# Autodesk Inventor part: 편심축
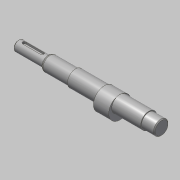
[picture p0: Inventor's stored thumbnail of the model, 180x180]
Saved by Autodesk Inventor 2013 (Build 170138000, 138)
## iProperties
Created: 2017-08
Part Number: 편심축
Material: 강철, 연강
Document SubType Name: Modeling
Designer: mduedu
Density: 7.86 g/cm^3
Mass: 338.399 g
Surface Area: 105.4 cm^2
Volume: 43.0533 cm^3
Author: mduedu
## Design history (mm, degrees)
sketch "스케치1"
  geometry: L1 (0, 0)-(168, 0); L2 (168, 0)-(168, 8.5); L3 (168, 8.5)-(153, 8.5); L4 (153, 8.5)-(153, 9.5); L5 (153, 9.5)-(67, 9.5); L6 (67, 9.5)-(67, 8.5); L7 (67, 8.5)-(35, 8.5); L8 (35, 8.5)-(35, 6); L9 (35, 6)-(0, 6); L10 (0, 6)-(0, 0)
  constraints: 20 end point, 6 parallel, 2 collinear, 2 perpendicular, 1 horizontal
  dimensions: "d0" = 168 distance of L1.start L1.end; "d1" = 17 diameter of L3 L1; "d2" = 19 diameter of L5 L1; "d3" = 12 diameter of L9 L1; "d4" = 35 distance of L8.end L9.end; "d5" = 15 distance of L2.end L3.end; "d6" = 86 distance of L4.end L5.end
revolve "회전1" sketch "스케치1" stored, may be unused: angle "d7" = 90 deg
node "작업 평면1"
sketch "스케치2"
  geometry: C1 r 9.5 at (0, 0) reference; C2 r 13 at (0, -3.5); 1 further point
  constraints: 1 centre point, 1 tangent, 1 vertical alignment
  dimensions: "d8" = 3.5 distance of point (0, 0) C2.centre
extrude "돌출1" join sketch "스케치2" stored distance "d9" = 18; taper "d10" = 0 deg
chamfer "모따기1" distance "d11" = 1; stored, may be unused: second distance "d12" = 2, angle "d13" = 45 deg
node "작업 평면2"
sketch "스케치3"
  geometry: L1 (10.5, -2)-(-10.5, -2); L2 (-10.5, -2)-(-10.5, 2); L3 (-10.5, 2)-(10.5, 2); L4 (10.5, 2)-(10.5, -2); L5 (17.5, 6)-(17.5, -6) reference; L6 (-17.5, 8.5)-(-17.5, -8.5) reference; A1 r 2 centre (10.5, 0) between (10.5, -2) and (10.5, 2); A2 r 2 centre (-10.5, 0) between (-10.5, 2) and (-10.5, -2); A3 r 2 centre (10.5, 0) between (10.5, 2) and (10.5, -2); A4 r 2 centre (-10.5, 0) between (-10.5, -2) and (-10.5, 2); 1 further point
  constraints: 8 end point, 8 point on circle, 4 centre point, 2 midpoint, 2 parallel, 1 horizontal, 1 horizontal alignment, 1 perpendicular
  dimensions: "d14" = 25 dimension on A2 A1; "d16" = 4 distance between parallel lines of L3 L1; "d17" = 5 distance edge to line of A1 L5; "d46" = 5 distance edge to line of A2 L6 (derived)
extrude "돌출2" cut sketch "스케치3" distance "d18" = 2.5; taper "d19" = 0 deg
chamfer "모따기2" distance "d20" = 1; stored, may be unused: second distance "d21" = 2, angle "d22" = 45 deg
chamfer "모따기4" distance "d39" = 1.82; stored, may be unused: second distance "d40" = 2, angle "d41" = 30 deg
fillet "모깎기4" dims "d45" = 2
hole "구멍1" diameter "d29" = 3.242; stored, may be unused: countersink angle "d33" = 90 deg, drill point angle "d35" = 118 deg; dims "d30" = 8, "d31" = 4, "d32" = 2, "d34" = 10, "d36" = 10, "d37" = 10
node "솔리드1"
node "절단 모서리 투영1"
